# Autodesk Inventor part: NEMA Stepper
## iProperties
Author: SCHNEIDER.K
Shininess: 20.0
PropertySet Name: _Private Model Information
Part Number: NEMA Stepper
Document SubType Name: Modeling
Designer: SCHNEIDER.K
Control State: 0
Master: False
Checked Out: False
PropertySet Name: Design Tracking Control
Density: 0.0
Volumn: 0.0
Area: 0.0
PropertySet Name: Model Information
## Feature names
1. Extrusion1
2. Hole1
3. Fillet1
4. Extrusion2
5. Extrusion3
6. Extrusion4
7. Extrusion5
8. Shaft2 [Extrusion]
9. HousingFillet [Fillet]
10. ElecConn [Extrusion]
11. ElecHole [Hole]
